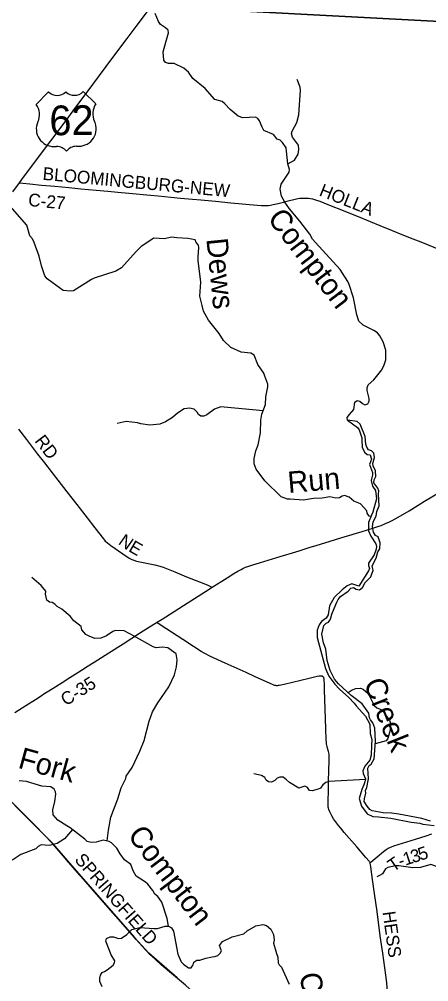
# Model space of a CAD drawing. Extents: x -51392 to 1635000, y 156707 to 696232.
# Drawn here: x 159345 to 168915, y 495829 to 518358 of the extents above; entities that cross this region are included whole.
import ezdxf

# ---------------------------------------------------------------- set-up
doc = ezdxf.new("R2010")
doc.units = 0
for name, color, linetype in [('GM_X_County_Road', 7, 'Continuous'), ('GM_X_County_Road_Text', 7, 'Continuous'), ('GM_X_Minor_River', 7, 'Continuous'), ('GM_X_Minor_River_Text', 7, 'Continuous'), ('GM_X_Township', 7, 'Continuous'), ('GM_X_Township_Road', 7, 'Continuous'), ('GM_X_Township_Road_Text', 7, 'Continuous'), ('GM_X_US_Route', 7, 'Continuous'), ('GM_X_US_Shield', 7, 'Continuous')]:
    doc.layers.add(name, color=color, linetype=linetype)

msp = doc.modelspace()

# ---------------------------------------------------------------- linework, layer by layer
at = {"layer": 'GM_X_County_Road'}
for points in [[(159351, 514527), (159427, 514520), (159590, 514503), (159867, 514477), (160178, 514447), (160504, 514417), (160782, 514392), (161141, 514359), (161419, 514333), (161647, 514311), (161908, 514286), (162414, 514238), (162594, 514222), (162888, 514194), (163117, 514173), (163394, 514148), (163590, 514131), (163672, 514124), (163932, 514099), (164290, 514064), (164909, 514006), (165007, 513999), (165072, 513996), (165121, 513997), (165170, 514001), (165219, 514008), (165283, 514019), (165395, 514044), (165522, 514076), (165633, 514104), (165792, 514144), (165857, 514159), (165905, 514167), (165955, 514172), (166004, 514173), (166054, 514172), (166103, 514168), (166152, 514161), (166200, 514152), (166249, 514140), (166296, 514126), (166373, 514098), (166556, 514025), (166951, 513865), (167361, 513698), (167544, 513625), (167772, 513533), (168061, 513416), (168289, 513322), (168547, 513219), (168730, 513146), (168867, 513090), (169338, 512898)], [(163852, 505062), (164206, 505284), (164360, 505382), (164457, 505442), (164529, 505481), (164574, 505503), (164633, 505530), (164710, 505560), (164804, 505589), (164960, 505637), (165368, 505762), (165886, 505918), (166122, 505990), (166310, 506048), (166592, 506134), (166759, 506186), (166941, 506242), (167129, 506297), (167254, 506337), (167333, 506362), (167632, 506452), (167725, 506483), (167802, 506512), (167909, 506555), (167999, 506595), (168058, 506623), (168131, 506662), (168259, 506735), (168456, 506853), (168666, 506981), (168820, 507076), (169198, 507306)], [(162556, 504236), (162682, 504317), (162962, 504495), (163183, 504636), (163529, 504854), (163696, 504960), (163852, 505062)], [(159238, 502133), (159502, 502299), (159723, 502439), (159807, 502493), (159945, 502581), (160037, 502639), (160196, 502741), (160348, 502837), (160526, 502950), (160653, 503030), (160800, 503123), (160955, 503220), (161093, 503307), (161438, 503527), (161770, 503738), (161978, 503869), (162159, 503985), (162393, 504133), (162532, 504220), (162556, 504236)], [(163228, 495747), (162902, 496021), (162665, 496223), (162518, 496355), (162400, 496469), (162299, 496577), (162080, 496821), (161864, 497068), (161756, 497191), (161592, 497374), (161094, 497941), (160954, 498102), (160763, 498327), (160452, 498686), (160334, 498823), (160206, 498972), (160119, 499070), (159995, 499201), (159821, 499375), (159440, 499759), (159245, 499958)]]:
    msp.add_lwpolyline(points, dxfattribs=at)
at = {"layer": 'GM_X_Minor_River'}
for points in [[(167012, 509040), (167066, 509106), (167162, 509222), (167190, 509394), (167246, 509432), (167304, 509420), (167366, 509362), (167420, 509336), (167490, 509356), (167524, 509420), (167522, 509484), (167478, 509666), (167474, 509730), (167500, 509799), (167630, 509917), (167818, 510153), (167876, 510271), (167910, 510387), (167914, 510439), (167914, 510616), (167853, 510804), (167775, 510948), (167717, 511015), (167631, 511073), (167381, 511197), (167285, 511293), (167233, 511440), (167157, 511835), (167055, 512151), (167025, 512219), (166847, 512504), (166270, 513134), (166202, 513210), (166134, 513330), (165906, 513631), (165662, 513918), (165552, 514078), (165476, 514215), (165442, 514377), (165466, 514497), (165650, 514782), (165658, 514838), (165623, 514970), (165595, 515273), (165581, 515349), (165501, 515475), (165443, 515525), (165375, 515553), (165287, 515664), (165065, 515754), (165023, 515832), (164961, 515979), (164921, 516033), (164865, 516065), (164573, 516051), (164461, 516091), (164271, 516246), (164153, 516374), (164087, 516432), (163915, 516479), (163687, 516737), (163401, 516974), (163304, 517120), (163252, 517160), (163190, 517209), (162968, 517325), (162836, 517323), (162764, 517343), (162726, 517399), (162708, 517598), (162772, 517818), (162834, 518041), (162824, 518099), (162766, 518159), (162644, 518237), (162598, 518303), (162524, 518494)], [(165623, 514970), (165775, 515058), (165861, 515198), (165883, 515306), (165869, 515411), (165733, 515601), (165707, 515681), (165721, 515737), (165829, 515942), (165879, 516124), (165915, 516699), (165914, 516771), (165842, 516949)], [(167565, 506716), (167520, 506723), (167476, 506795), (167468, 506851), (167318, 507012), (167165, 507078), (167053, 507172), (166945, 507208), (166889, 507192), (166831, 507152), (166741, 507150), (166607, 507181), (166426, 507145), (166222, 507141), (165988, 507103), (165678, 507122), (165616, 507122), (165464, 507180), (165085, 507553), (164885, 507824), (164833, 507950), (164833, 508074), (164871, 508256), (164929, 508395), (164985, 508677), (164993, 508972), (165013, 509116), (165104, 509338), (165112, 509523), (165156, 509753), (165152, 509817), (165110, 509943), (165086, 510005), (165060, 510070), (164924, 510276), (164832, 510493), (164760, 510545), (164530, 510565), (164292, 510674), (164118, 510842), (164020, 511000), (163766, 511315), (163649, 511524), (163621, 511660), (163563, 511877), (163589, 512207), (163523, 512708), (163527, 512788), (163545, 513015), (163533, 513071), (163481, 513133), (163457, 513193), (163289, 513225), (163029, 513244), (162905, 513258), (162739, 513218), (162487, 513232), (162193, 513040), (162077, 512922), (161733, 512538), (161599, 512460), (161095, 512300), (161033, 512270), (160615, 511998), (160549, 511990), (160371, 512006), (160115, 512195), (159999, 512283), (159943, 512351), (159863, 512588), (159809, 512812), (159693, 513131), (159651, 513221), (159591, 513291), (159525, 513536), (159134, 513979)], [(165045, 509191), (164133, 509281), (164059, 509285), (163909, 509235), (163727, 509095), (163657, 509069), (163587, 509071), (163533, 509109), (163501, 509164), (163433, 509228), (163327, 509258), (163203, 509238), (163047, 509138), (162925, 509034), (162767, 508932), (162631, 508882), (162397, 508858), (162183, 508885), (162109, 508909), (161845, 508939), (161633, 508897)], [(168957, 499591), (168753, 499650), (168213, 499749), (168047, 499779), (167851, 499781), (167593, 499831), (167541, 499864), (167479, 499936), (167409, 500050), (167417, 500114), (167443, 500242), (167439, 500309), (167469, 500375), (167507, 500577), (167489, 500832), (167521, 500888), (167573, 500922), (167641, 501050), (167672, 501459), (167656, 501767), (167606, 501892), (167558, 501958), (167530, 502010), (167514, 502118), (167358, 502331), (167100, 502529), (166808, 502806), (166712, 502908), (166612, 503115), (166545, 503345), (166513, 503610), (166457, 503760), (166415, 503967), (166461, 504165), (166517, 504223), (166571, 504247), (166619, 504315), (166649, 504433), (166741, 504662), (166771, 504716), (166795, 504780), (166853, 504846), (167035, 504972), (167095, 505038), (167155, 505054), (167223, 505016), (167299, 505000), (167365, 505056), (167432, 505178), (167560, 505306), (167584, 505374), (167618, 505452), (167596, 505563), (167684, 505743), (167724, 505889), (167774, 505961), (167782, 506101), (167734, 506240), (167674, 506278), (167624, 506356), (167602, 506474), (167620, 506598), (167686, 506725), (167704, 506837), (167760, 506969), (167743, 507242), (167747, 507318), (167729, 507384), (167631, 507510), (167641, 507580), (167677, 507652), (167673, 507785), (167615, 507903), (167613, 507959), (167649, 508097), (167629, 508201), (167575, 508256), (167509, 508278), (167467, 508342), (167445, 508412), (167431, 508590), (167311, 508879), (167245, 508939), (167017, 508974)], [(167017, 508974), (167012, 509040)], [(167017, 508974), (167249, 508801), (167289, 508745), (167351, 508562), (167353, 508506), (167361, 508340), (167417, 508224), (167475, 508174), (167547, 508161), (167577, 508061), (167533, 507935), (167605, 507747), (167601, 507693), (167569, 507562), (167599, 507430), (167671, 507326), (167693, 507129), (167606, 506823), (167578, 506753), (167510, 506575)], [(167510, 506575), (167504, 506386), (167566, 506256), (167676, 506083), (167694, 506027), (167686, 505951), (167638, 505823), (167508, 505625), (167508, 505569), (167532, 505501), (167508, 505448), (167279, 505092), (167119, 505142), (167063, 505118), (167011, 505098), (166893, 505006), (166709, 504824), (166595, 504626), (166569, 504418), (166519, 504341), (166413, 504263), (166355, 504187), (166311, 504059), (166305, 503885), (166502, 503159), (166582, 502983), (166720, 502796), (166828, 502680), (167050, 502485), (167170, 502349), (167222, 502289), (167434, 502044), (167540, 501862), (167550, 501637), (167584, 501501), (167580, 501367), (167572, 501132), (167539, 501014), (167421, 500878), (167379, 500768), (167387, 500707), (167437, 500581), (167425, 500507), (167399, 500441), (167349, 500329), (167289, 500120), (167343, 499940), (167477, 499761), (167611, 499697), (167743, 499687), (168029, 499655), (168505, 499566), (168707, 499544), (168779, 499517), (169045, 499485)], [(161398, 499124), (161428, 499375), (161482, 499678), (161651, 500112), (161727, 500365), (161833, 500587), (161845, 500641), (161983, 500846), (162167, 501228), (162267, 501473), (162381, 501925), (162456, 502150), (162584, 502354), (162840, 502736), (162974, 503015), (163018, 503197), (163038, 503363), (163010, 503508), (162958, 503544), (162818, 503648), (162686, 503658), (162548, 503646), (162474, 503669), (162030, 503915), (161797, 504042), (161596, 504052), (161530, 504026), (161384, 503926), (161252, 503868), (161108, 503860), (160980, 503917), (160900, 503959), (160806, 504067), (160794, 504141), (160619, 504280), (160531, 504388), (160343, 504550), (160229, 504613), (160177, 504667), (160111, 504703), (160049, 504711), (159991, 504763), (159955, 504898), (159963, 504968), (159859, 505104), (159637, 505295)], [(167031, 502600), (167130, 502662), (167210, 502692), (167318, 502703), (167386, 502681), (167502, 502577), (167640, 502294), (167700, 502240), (167762, 502214), (167832, 502182), (167996, 501945), (168026, 501865), (168018, 501715), (167960, 501522), (167922, 501466), (167667, 501395)], [(167438, 500561), (166581, 500516), (166511, 500492), (166443, 500440), (166383, 500364), (166333, 500334), (166193, 500300), (166127, 500308), (166085, 500372), (166021, 500410), (165877, 500360), (165663, 500491), (165593, 500555), (165517, 500615), (165437, 500617), (165373, 500593), (165315, 500541), (165239, 500503), (165167, 500509), (165113, 500550), (165083, 500608), (165009, 500654), (164825, 500694)], [(162837, 497133), (162805, 497307), (162681, 497694), (162583, 497825), (162512, 497883), (162466, 497965), (162350, 498112), (162296, 498162), (162078, 498302), (162010, 498425), (161954, 498571), (161808, 498683), (161704, 498820), (161626, 498958), (161572, 499010), (161500, 499080), (161448, 499115), (161306, 499143), (161140, 499099), (161028, 499089), (160932, 499109), (160876, 499169), (160538, 499434), (160456, 499480), (160244, 499611), (160138, 499733), (160128, 499856), (160176, 500048), (160198, 500222), (160194, 500276), (160159, 500339), (160085, 500393), (159869, 500407), (159515, 500516), (159341, 500534)], [(160589, 499392), (160400, 499172), (160230, 499062), (160046, 499022), (159854, 499036), (159786, 498998), (159732, 498944), (159378, 498810), (159192, 498680), (158940, 498590), (158812, 498492), (158577, 498442), (158513, 498404), (158401, 498392), (158253, 498324), (158119, 498234), (157975, 497990), (157987, 497914), (158103, 497723), (158129, 497657), (158131, 497593)], [(169617, 498292), (169528, 498348), (169454, 498380), (169360, 498487), (169168, 498505), (168966, 498571), (168726, 498507), (168544, 498492), (168216, 498540), (168140, 498542), (167960, 498504), (167906, 498472), (167832, 498356), (167768, 498318), (167702, 498288)], [(161280, 495709), (161232, 495834), (161226, 495916), (161245, 495984), (161285, 496044), (161337, 496072), (161401, 496110), (161537, 496216), (161569, 496270), (161575, 496320), (161491, 496461), (161371, 496776), (161383, 496844), (161469, 496884), (161547, 496878), (161667, 496844), (161733, 496851), (161859, 496932), (161975, 497052), (162165, 497100), (162493, 497075), (162573, 497075), (162753, 497129), (162837, 497133), (162901, 497093), (162949, 497015), (163051, 496477), (163133, 496293), (163181, 496239), (163299, 496152), (163361, 496154), (163411, 496226), (163423, 496290), (163499, 496334), (163563, 496334), (163703, 496382), (163855, 496412), (163913, 496420), (163985, 496444), (164043, 496496), (164073, 496556), (164023, 496679), (164097, 496775), (164325, 496877), (164597, 496953), (164671, 497021), (164875, 497141), (165037, 497169), (165123, 497146), (165227, 497062), (165285, 496936), (165303, 496800), (165291, 496729), (165339, 496545), (165355, 496487), (165387, 496405), (165399, 496272), (165419, 496222), (165477, 496172), (165653, 495769)]]:
    msp.add_lwpolyline(points, dxfattribs=at)
at = {"layer": 'GM_X_Township'}
for points in [[(177580, 517864), (162392, 518660), (156896, 518947), (156648, 518960), (156580, 519550), (155872, 525660), (155251, 531033), (154449, 537962), (154393, 538443), (153721, 544251), (153416, 546885), (154887, 546778), (157022, 546663), (159649, 546538), (163080, 546381), (166694, 546239), (167692, 546175), (177006, 545575)], [(164490, 494623), (163036, 495918), (162375, 496499), (162038, 496867), (160576, 498540), (160125, 499063), (159714, 499486), (159105, 500105), (158676, 500430), (158040, 500911), (157691, 501158), (157429, 501318), (157103, 501507), (156897, 501677), (156249, 502283), (156062, 502444), (155960, 502573), (155421, 503418), (155247, 503773), (155787, 509753), (155947, 511459), (156029, 512335), (156615, 518610)], [(162392, 518660), (177580, 517864)], [(159105, 500105), (159714, 499486), (160125, 499063), (160576, 498540), (162038, 496867), (162375, 496499), (163036, 495918), (164490, 494623)]]:
    msp.add_lwpolyline(points, dxfattribs=at)
at = {"layer": 'GM_X_Township_Road'}
for points in [[(159324, 508765), (159515, 508518), (159775, 508180), (159936, 507973), (160117, 507739), (160456, 507296), (160688, 506998), (160930, 506687), (161110, 506454), (161312, 506194), (161335, 506168), (161355, 506145), (161375, 506127), (161405, 506102), (161483, 506043), (161768, 505848), (161917, 505747), (161974, 505715), (162020, 505695), (162082, 505676), (162242, 505639), (162516, 505584), (162627, 505557), (162706, 505533), (162828, 505485), (162979, 505422), (163253, 505310), (163557, 505190), (163620, 505164), (163755, 505109), (163829, 505074), (163852, 505062)], [(167543, 498614), (167538, 498626), (167530, 498639), (167520, 498654), (167446, 498741), (167232, 498990), (166943, 499326), (166858, 499425), (166805, 499486), (166734, 499577), (166688, 499644), (166647, 499715), (166603, 499804), (166579, 499864), (166570, 499896), (166567, 499912), (166564, 499929), (166563, 499941), (166563, 499959), (166566, 500091), (166571, 500271), (166576, 500517), (166583, 500780), (166589, 500993), (166590, 501108), (166589, 501138), (166588, 501158), (166583, 501188), (166574, 501221), (166550, 501299), (166539, 501337), (166533, 501363), (166530, 501385), (166527, 501405), (166524, 501439), (166521, 501493), (166513, 501756), (166505, 501985), (166482, 502660), (166477, 502814), (166473, 502869), (166471, 502912), (166470, 502922), (166467, 502936), (166463, 502945), (166460, 502952), (166455, 502958), (166450, 502964), (166444, 502969), (166437, 502974), (166429, 502978), (166422, 502981), (166414, 502983), (166406, 502984), (166390, 502985), (166357, 502983), (166309, 502973), (166122, 502930), (165534, 502787), (165422, 502763), (165397, 502760), (165373, 502758), (165357, 502759), (165340, 502760), (165325, 502763), (165308, 502767), (165262, 502784), (164859, 502969), (164650, 503064), (164158, 503289), (163816, 503445), (163670, 503520), (163599, 503561), (163420, 503677), (163172, 503837), (162774, 504098), (162594, 504213), (162556, 504236)], [(167543, 498614), (167570, 498637), (167708, 498752), (167859, 498878), (167924, 498928), (167965, 498954), (167988, 498965), (168010, 498975), (168048, 498988), (168103, 499007), (168400, 499101), (168603, 499165), (168852, 499247), (168992, 499294)], [(168307, 492431), (168300, 492524), (168273, 492752), (168213, 493224), (168148, 493745), (168128, 493907), (168111, 494038), (168082, 494265), (168062, 494412), (168025, 494705), (168004, 494950), (167953, 495571), (167934, 495800), (167915, 495980), (167842, 496500), (167784, 496906), (167707, 497475), (167645, 497898), (167601, 498225), (167561, 498517), (167554, 498565), (167549, 498595), (167544, 498611), (167543, 498614)]]:
    msp.add_lwpolyline(points, dxfattribs=at)
at = {"layer": 'GM_X_US_Route'}
msp.add_lwpolyline([(159194, 514317), (159351, 514527), (159447, 514659), (160084, 515514), (160438, 515987), (160604, 516212), (161064, 516830), (161535, 517463), (161868, 517909), (162075, 518186), (162340, 518539)], dxfattribs=at)
at = {"layer": 'GM_X_US_Shield'}
for p, q in [((160029, 516656), (159742, 516363)), ((161134, 516376), (160841, 516663)), ((160157, 515381), (160215, 515381)), ((160679, 515385), (160737, 515386))]:
    msp.add_line(p, q, dxfattribs=at)
for centre, radius, start, end in [((160230, 516865), 290, 226.1115, 314.9656), ((160636, 516868), 290, 226.1115, 314.9656), ((159412, 516127), 406, 335.0857, 35.5395), ((161469, 516146), 406, 145.5376, 205.9914), ((160149, 515786), 406, 155.3705, 271.1768), ((160738, 515792), 406, 269.9003, 25.7066), ((160218, 515091), 290, 37.4084, 90.5385), ((160682, 515095), 290, 90.5385, 143.6686)]:
    msp.add_arc(centre, radius, start, end, dxfattribs=at)

# ---------------------------------------------------------------- texts
at = {"layer": 'GM_X_County_Road_Text'}
for s, rotation, p in [('BLOOMINGBURG-NEW', 354.652, (159882, 514601)), ('HOLLA', 338.3256, (166335, 514237)), ('C-27', 354.3937, (159544, 513989)), ('C-35', 32.3247, (160434, 502274)), ('SPRINGFIELD', 311.1283, (160621, 498676))]:
    msp.add_text(s, height=300, rotation=rotation, dxfattribs=at).set_placement(p)
at = {"layer": 'GM_X_Minor_River_Text'}
for s, height, rotation, p in [('Compton', 500, 307.3916, (165128, 513692)), ('Dews', 500, 275.7551, (163717, 513215)), ('Run', 500, 4.9301, (165639, 507267)), ('Creek', 500, 291.7263, (167388, 502825)), ('Fork', 500, 344.5487, (159294, 500841)), ('Compton', 500.1, 307.3848, (161859, 499253)), ('Creek', 500.1, 279.7265, (165892, 496005))]:
    msp.add_text(s, height=height, rotation=rotation, dxfattribs=at).set_placement(p)
at = {"layer": 'GM_X_Township_Road_Text'}
for s, rotation, p in [('RD', 307.5061, (159691, 508485)), ('N', 324.8679, (161639, 506085)), ('E', 330.0465, (161880, 505917)), ('1', 17.9959, (168368, 498545)), ('3', 17.9745, (168544, 498602)), ('5', 17.9745, (168720, 498659)), ('T', 34.7908, (168088, 498389)), ('-', 18.0281, (168251, 498507)), ('HESS', 277.8375, (167835, 497461))]:
    msp.add_text(s, height=300, rotation=rotation, dxfattribs=at).set_placement(p)
at = {"layer": 'GM_X_US_Shield'}
msp.add_text('62', height=696.1, rotation=0.5385, dxfattribs=at).set_placement((160051, 515641))

doc.saveas('drawing.dxf')
